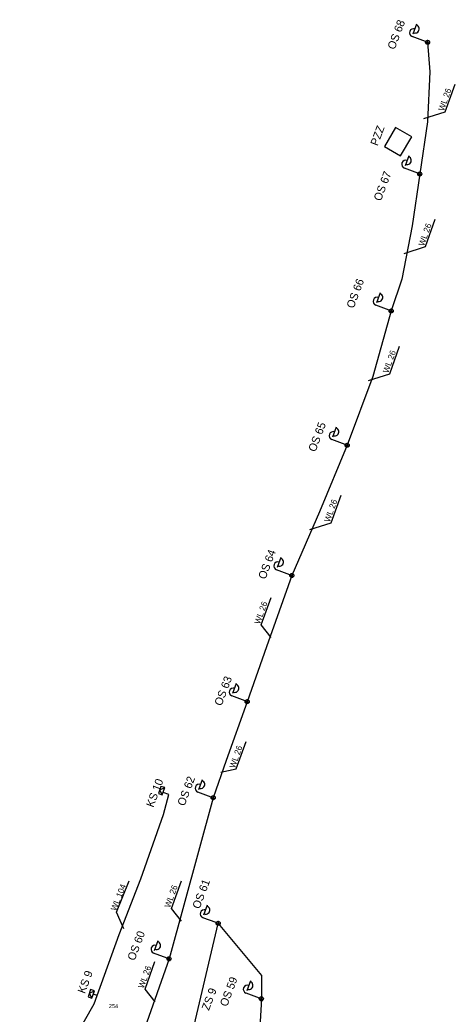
# Model space of a CAD drawing. Extents: x -695448 to -695200, y -1124997 to -1123857.
# Drawn here: x -695308.5 to -695199.8, y -1124105.2 to -1123856.9 of the extents above; entities that cross this region are included whole.
import ezdxf

# ---------------------------------------------------------------- set-up
doc = ezdxf.new("R2010")
doc.units = 0
doc.layers.add('Vrstva 26', color=7, linetype='Continuous')

msp = doc.modelspace()

# ---------------------------------------------------------------- linework, layer by layer
at = {"layer": 'Vrstva 26'}
for p, q in [((-695210.25, -1123860.41), (-695209.33, -1123857.92)), ((-695207.14, -1123862.33), (-695210.5, -1123861.08)), ((-695206.69, -1123863.01), (-695207.07, -1123862.2)), ((-695206.33, -1123862.89), (-695206.74, -1123862)), ((-695212.21, -1123893.28), (-695211.29, -1123890.79)), ((-695209.1, -1123895.19), (-695212.46, -1123893.95)), ((-695208.65, -1123895.88), (-695209.03, -1123895.06)), ((-695208.29, -1123895.75), (-695208.7, -1123894.87)), ((-695219.35, -1123927.5), (-695218.43, -1123925.01)), ((-695216.24, -1123929.41), (-695219.6, -1123928.17)), ((-695215.79, -1123930.1), (-695216.17, -1123929.28)), ((-695215.43, -1123929.97), (-695215.84, -1123929.09)), ((-695230.34, -1123961.05), (-695229.42, -1123958.56)), ((-695227.24, -1123962.97), (-695230.59, -1123961.72)), ((-695226.79, -1123963.65), (-695227.16, -1123962.84)), ((-695226.42, -1123963.53), (-695226.83, -1123962.64)), ((-695244.16, -1123993.58), (-695243.24, -1123991.09)), ((-695241.06, -1123995.49), (-695244.41, -1123994.25)), ((-695240.61, -1123996.18), (-695240.98, -1123995.37)), ((-695240.24, -1123996.06), (-695240.65, -1123995.17)), ((-695255.33, -1124025.09), (-695254.41, -1124022.6)), ((-695252.22, -1124027.01), (-695255.58, -1124025.77)), ((-695251.77, -1124027.69), (-695252.15, -1124026.88)), ((-695251.41, -1124027.57), (-695251.82, -1124026.68)), ((-695263.83, -1124049.1), (-695262.91, -1124046.61)), ((-695260.72, -1124051.01), (-695264.08, -1124049.77)), ((-695260.27, -1124051.7), (-695260.65, -1124050.89)), ((-695259.91, -1124051.58), (-695260.32, -1124050.69)), ((-695262.57, -1124080.47), (-695261.65, -1124077.97)), ((-695259.46, -1124082.38), (-695262.82, -1124081.14)), ((-695259.01, -1124083.07), (-695259.39, -1124082.25)), ((-695258.65, -1124082.94), (-695259.06, -1124082.05)), ((-695274.86, -1124089.33), (-695273.94, -1124086.83)), ((-695271.75, -1124091.24), (-695275.11, -1124090)), ((-695271.3, -1124091.93), (-695271.68, -1124091.11)), ((-695270.94, -1124091.8), (-695271.35, -1124090.91)), ((-695251.78, -1124099.31), (-695250.86, -1124096.81)), ((-695248.67, -1124101.22), (-695252.03, -1124099.98)), ((-695248.22, -1124101.91), (-695248.6, -1124101.09)), ((-695247.86, -1124101.78), (-695248.27, -1124100.89))]:
    msp.add_line(p, q, dxfattribs=at)
for points in [[(-695206.66, -1123862.5), (-695206.13, -1123869.85), (-695206.7, -1123882.37), (-695208.62, -1123895.37), (-695210.54, -1123908.37), (-695213.11, -1123921.65), (-695215.76, -1123929.59), (-695220.34, -1123945.95), (-695226.76, -1123963.14), (-695233.64, -1123979.75), (-695240.58, -1123995.67), (-695246.89, -1124013.5), (-695251.74, -1124027.2), (-695256.96, -1124041.92), (-695260.24, -1124051.19), (-695271.27, -1124091.42), (-695277.35, -1124108.62)], [(-695207.57, -1123881.56), (-695202.23, -1123879.83), (-695199.77, -1123872.98)], [(-695212.53, -1123915.28), (-695207.19, -1123913.54), (-695204.73, -1123906.69)], [(-695221.44, -1123947.01), (-695216.1, -1123945.27), (-695213.64, -1123938.42)], [(-695236.09, -1123984.23), (-695230.75, -1123982.49), (-695228.29, -1123975.65)], [(-695245.73, -1124011.19), (-695248.2, -1124007.99), (-695245.74, -1124001.14)], [(-695258.34, -1124044.84), (-695254.46, -1124043.99), (-695252, -1124037.14)], [(-695308.54, -1124136.53), (-695308.08, -1124136.67), (-695296.85, -1124114.85), (-695290.01, -1124102.66), (-695289.25, -1124100.57), (-695283.71, -1124085.37), (-695278.28, -1124071.41), (-695272.66, -1124055.34), (-695271.28, -1124050.37), (-695272.74, -1124049.86)], [(-695272.95, -1124050.47), (-695273.59, -1124049.24), (-695272.34, -1124048.66)], [(-695282.57, -1124083.94), (-695284.39, -1124079.8), (-695281.25, -1124071.96)], [(-695268.17, -1124082.02), (-695270.64, -1124078.82), (-695268.18, -1124071.97)], [(-695280.29, -1124157.37), (-695287.98, -1124154.37), (-695280.71, -1124134.89), (-695278.55, -1124127.46), (-695271.44, -1124109.04), (-695266.59, -1124110.09), (-695264.96, -1124108.09), (-695258.98, -1124082.56), (-695248.12, -1124095.56), (-695248.19, -1124101.4), (-695249.91, -1124131.13)], [(-695274.77, -1124102.17), (-695277.24, -1124098.97), (-695274.78, -1124092.12)], [(-695308.54, -1124136.53), (-695308.08, -1124136.67), (-695296.85, -1124114.85), (-695290.01, -1124102.66), (-695289.25, -1124100.57), (-695290.19, -1124100.22)], [(-695290.53, -1124101.23), (-695291.17, -1124100.01), (-695289.91, -1124099.42)]]:
    msp.add_lwpolyline(points, dxfattribs=at)
for points in [[(-695210.63, -1123886.13), (-695214.67, -1123883.76), (-695217.45, -1123888.5), (-695213.41, -1123890.87)], [(-695272.95, -1124050.47), (-695272.34, -1124048.66), (-695273.29, -1124048.34), (-695273.9, -1124050.15)], [(-695290.52, -1124101.24), (-695289.91, -1124099.42), (-695290.86, -1124099.1), (-695291.47, -1124100.91)]]:
    msp.add_lwpolyline(points, close=True, dxfattribs=at)
for centre in [(-695206.66, -1123862.5), (-695206.66, -1123862.5), (-695208.62, -1123895.37), (-695208.62, -1123895.37), (-695215.76, -1123929.59), (-695215.76, -1123929.59), (-695226.76, -1123963.14), (-695226.76, -1123963.14), (-695240.58, -1123995.67), (-695240.58, -1123995.67), (-695251.74, -1124027.18), (-695251.74, -1124027.18), (-695260.24, -1124051.19), (-695260.24, -1124051.19), (-695258.98, -1124082.56), (-695258.98, -1124082.56), (-695271.27, -1124091.42), (-695271.27, -1124091.42), (-695248.19, -1124101.4), (-695248.19, -1124101.4)]:
    msp.add_circle(centre, 0.511, dxfattribs=at)
for centre, start, end in [((-695210.14, -1123860.12), 69.7051, 249.7051), ((-695209.78, -1123859.17), 249.0025, 70.4077), ((-695212.1, -1123892.99), 69.7051, 249.7051), ((-695211.74, -1123892.04), 249.0025, 70.4077), ((-695219.24, -1123927.21), 69.7051, 249.7051), ((-695218.88, -1123926.26), 249.0025, 70.4077), ((-695229.87, -1123959.81), 249.0025, 70.4077), ((-695230.24, -1123960.77), 69.7051, 249.7051), ((-695243.69, -1123992.34), 249.0025, 70.4077), ((-695244.06, -1123993.29), 69.7051, 249.7051), ((-695254.86, -1124023.85), 249.0025, 70.4077), ((-695255.22, -1124024.81), 69.7051, 249.7051), ((-695263.72, -1124048.81), 69.7051, 249.7051), ((-695263.36, -1124047.86), 249.0025, 70.4077), ((-695262.1, -1124079.23), 249.0025, 70.4077), ((-695262.46, -1124080.18), 69.7051, 249.7051), ((-695274.75, -1124089.04), 69.7051, 249.7051), ((-695274.39, -1124088.09), 249.0025, 70.4077), ((-695251.68, -1124099.02), 69.7051, 249.7051), ((-695251.31, -1124098.06), 249.0025, 70.4077)]:
    msp.add_arc(centre, 1.02, start, end, dxfattribs=at)

# ---------------------------------------------------------------- texts
for s, height, rotation, p in [('OS 68', 2, 69.4105, (-695214.89, -1123864.47)), ('WL 26', 1.5, 70.5598, (-695202.6, -1123879.79)), ('PZZ', 2, 69.4105, (-695219.15, -1123888.52)), ('OS 67', 2, 69.4105, (-695218.33, -1123902.3)), ('WL 26', 1.5, 70.5598, (-695207.55, -1123913.51)), ('OS 66', 2, 69.4105, (-695225.14, -1123929.12)), ('WL 26', 1.5, 70.5598, (-695216.47, -1123945.23)), ('OS 65', 2, 69.4105, (-695234.67, -1123964.95)), ('WL 26', 1.5, 70.5598, (-695231.11, -1123982.46)), ('OS 64', 2, 69.4105, (-695247.19, -1123996.79)), ('WL 26', 1.5, 70.5598, (-695248.57, -1124007.96)), ('OS 63', 2, 69.4105, (-695258.14, -1124028.4)), ('WL 26', 1.5, 70.5598, (-695254.82, -1124043.95)), ('OS 62', 2, 69.4105, (-695267.39, -1124053.4)), ('KS 10', 2, 69.4105, (-695275.19, -1124053.74)), ('WL 104', 1.5, 68.1219, (-695284.52, -1124079.56)), ('WL 26', 1.5, 70.5598, (-695271.01, -1124078.78)), ('OS 61', 2, 69.4105, (-695263.64, -1124079.11)), ('OS 60', 2, 69.4105, (-695279.87, -1124092.03)), ('WL 26', 1.5, 70.5598, (-695277.6, -1124098.93)), ('KS 9', 2, 69.4105, (-695292.31, -1124100.26)), ('OS 59', 2, 69.4105, (-695256.77, -1124103.5)), ('ZS 9', 2, 69.4105, (-695261.3, -1124104.47))]:
    msp.add_text(s, height=height, rotation=rotation, dxfattribs=at).set_placement(p)
msp.add_text('254', height=1, dxfattribs=at).set_placement((-695286.31, -1124103.73))

doc.saveas('drawing.dxf')
